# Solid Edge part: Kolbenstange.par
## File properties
Username: bmolnar
Dokumentum tartalom típus: 0
Author: bmolnar
Last saved by: bmolnar
Revision: 80
Sűrűség: 0,000 kg/m^3
Pontosság: 0,990
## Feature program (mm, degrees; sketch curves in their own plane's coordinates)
base feature "unnamed BaseFeature 1"
sketch for "unnamed Protrusion 1" plane through (0, 0, -17.4) normal (0, 0, -1) x-axis (0, 1, 0)
  circle centre (0, 0) radius 20
extrude "unnamed Protrusion 1" add finite 17.45 along +normal
sketch for "Kihúzás_2" #1 plane through (0, 0, -17.4) normal (0, 0, -1) x-axis (0, 1, 0)
  circle centre (0, 0) radius 6
sketch for "Kihúzás_2" #2 plane through (0, 0, -17.4) normal (0, 0, -1) x-axis (0, 1, 0)
  circle centre (0, 0) radius 20
extrude "Kihúzás_2" add finite 12.55 along -normal
sketch for "Furat_1" plane through (0, 0, 29.9) normal (0, 0, 1) x-axis (0, -1, 0)
  hole centre (0, 0) bore radius 2.4585
hole "Furat_1" nominal diameter 6 finite  ThreadDepth = 12.5 mm; VBottomAngle = 118 deg
chamfer "Letörés_1" setback 0.5  SetBackValue2 = 45 deg
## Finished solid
Body 1: solid body, 17 faces, 23 edges, 8 vertices.
  Faces by surface: plane 7, cylinder 5, cone 3, torus 2
  Edges by curve: circle 13, line 6, curve on surface 2, ellipse 2
Bounding box of the edges (mm; curved faces can reach further): 40.000 x 40.000 x 67.250, from (-20, -20, -34.85) to (20, 20, 32.4).
Cylindrical faces by radius (mm): R2.4585 x2, R3.125 x1, R6 x1, R20 x1
Conical faces (half-angle, radius in mm at the cone's reference point): 45 deg R2.9585 x1, 45 deg R3.225 x1, 59 deg R2.4585 x1
Toroidal faces (ring radius, tube radius in mm): R2.925 r0.2 x1, R4.7 r1.3 x1
Planar faces by outward normal: +x 1, +z 2, -x 1, -z 1, oblique 2
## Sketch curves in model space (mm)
circle centre (0, 0, -17.4) radius 6
circle centre (0, 0, -17.4) radius 20
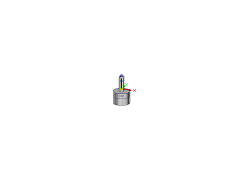
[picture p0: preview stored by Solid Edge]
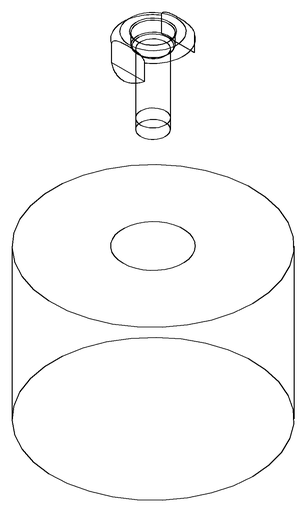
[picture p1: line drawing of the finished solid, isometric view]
